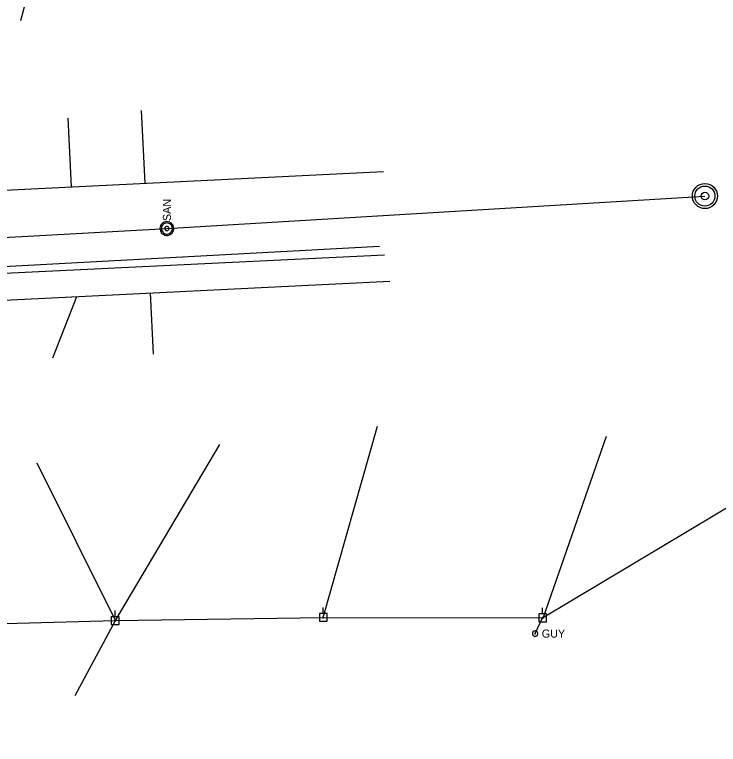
# Model space of a CAD drawing. Extents: x 596028 to 606371, y 330010 to 403088.
# Drawn here: x 605113.7 to 605450, y 333973.9 to 334322.4 of the extents above; entities that cross this region are included whole.
import ezdxf

# ---------------------------------------------------------------- set-up
doc = ezdxf.new("R2010")
doc.units = 0
for name, color, linetype in [('E_UTL_EGuyWire', 7, 'Continuous'), ('E_UTL_EPowerPole', 7, 'Continuous'), ('E_UTL_G_UG', 7, 'Continuous'), ('E_UTL_Overhead', 7, 'Continuous'), ('E_UTL_SAN_MH', 7, 'Continuous'), ('E_UTL_SAN_UG', 7, 'Continuous'), ('E_UTL_W_UG', 7, 'Continuous')]:
    doc.layers.add(name, color=color, linetype=linetype)

msp = doc.modelspace()

# ---------------------------------------------------------------- linework, layer by layer
at = {"layer": 'E_UTL_EGuyWire'}
msp.add_line((605362.42, 334026.83), (605366.02, 334034.35), dxfattribs=at)
for points in [[(605363.7, 334026.83), (605363.68, 334027.07), (605363.61, 334027.31), (605363.5, 334027.53), (605363.34, 334027.72), (605363.16, 334027.88), (605362.95, 334028), (605362.72, 334028.08), (605362.48, 334028.11), (605362.23, 334028.1), (605362, 334028.04), (605361.77, 334027.94), (605361.58, 334027.8), (605361.41, 334027.63), (605361.28, 334027.42), (605361.18, 334027.19), (605361.14, 334026.95), (605361.14, 334026.71), (605361.18, 334026.47), (605361.28, 334026.24), (605361.41, 334026.04), (605361.58, 334025.86), (605361.77, 334025.72), (605362, 334025.62), (605362.23, 334025.56), (605362.48, 334025.55), (605362.72, 334025.58), (605362.95, 334025.66), (605363.16, 334025.79), (605363.34, 334025.95), (605363.5, 334026.14), (605363.61, 334026.36), (605363.68, 334026.59), (605363.7, 334026.83)], [(605362.58, 334026.83), (605362.57, 334026.86), (605362.56, 334026.89), (605362.55, 334026.92), (605362.53, 334026.94), (605362.51, 334026.96), (605362.48, 334026.98), (605362.45, 334026.99), (605362.42, 334026.99), (605362.39, 334026.99), (605362.36, 334026.98), (605362.34, 334026.97), (605362.31, 334026.95), (605362.29, 334026.93), (605362.27, 334026.91), (605362.26, 334026.88), (605362.26, 334026.85), (605362.26, 334026.82), (605362.26, 334026.79), (605362.27, 334026.76), (605362.29, 334026.73), (605362.31, 334026.71), (605362.34, 334026.69), (605362.36, 334026.68), (605362.39, 334026.67), (605362.42, 334026.67), (605362.45, 334026.68), (605362.48, 334026.69), (605362.51, 334026.7), (605362.53, 334026.72), (605362.55, 334026.75), (605362.56, 334026.77), (605362.57, 334026.8), (605362.58, 334026.83)]]:
    msp.add_lwpolyline(points, dxfattribs=at)
at = {"layer": 'E_UTL_EPowerPole'}
for points in [[(605261.2, 334036.42), (605261.2, 334039.33)], [(605365.99, 334036.19), (605365.99, 334039.1)], [(605163.64, 334034.89), (605159.95, 334034.89)], [(605159.95, 334034.89), (605159.95, 334031.2)], [(605161.8, 334034.89), (605161.8, 334037.8)], [(605163.64, 334031.2), (605163.64, 334034.89)], [(605263.04, 334036.42), (605259.35, 334036.42)], [(605259.35, 334036.42), (605259.35, 334032.73)], [(605261.47, 334034.58), (605261.46, 334034.62), (605261.45, 334034.67), (605261.43, 334034.71), (605261.4, 334034.74), (605261.37, 334034.77), (605261.33, 334034.8), (605261.29, 334034.81), (605261.24, 334034.82), (605261.2, 334034.82), (605261.15, 334034.81), (605261.11, 334034.79), (605261.07, 334034.76), (605261.04, 334034.73), (605261.02, 334034.69), (605261, 334034.65), (605260.99, 334034.6), (605260.99, 334034.56), (605261, 334034.51), (605261.02, 334034.47), (605261.04, 334034.43), (605261.07, 334034.4), (605261.11, 334034.37), (605261.15, 334034.35), (605261.2, 334034.34), (605261.24, 334034.34), (605261.29, 334034.35), (605261.33, 334034.36), (605261.37, 334034.39), (605261.4, 334034.42), (605261.43, 334034.45), (605261.45, 334034.49), (605261.46, 334034.53), (605261.47, 334034.58)], [(605263.04, 334032.73), (605263.04, 334036.42)], [(605367.83, 334036.19), (605364.14, 334036.19)], [(605364.14, 334036.19), (605364.14, 334032.5)], [(605366.26, 334034.35), (605366.25, 334034.39), (605366.24, 334034.44), (605366.22, 334034.48), (605366.19, 334034.51), (605366.16, 334034.54), (605366.12, 334034.57), (605366.08, 334034.58), (605366.03, 334034.59), (605365.99, 334034.59), (605365.94, 334034.58), (605365.9, 334034.56), (605365.86, 334034.53), (605365.83, 334034.5), (605365.81, 334034.46), (605365.79, 334034.42), (605365.78, 334034.37), (605365.78, 334034.33), (605365.79, 334034.28), (605365.81, 334034.24), (605365.83, 334034.2), (605365.86, 334034.17), (605365.9, 334034.14), (605365.94, 334034.12), (605365.99, 334034.11), (605366.03, 334034.11), (605366.08, 334034.12), (605366.12, 334034.13), (605366.16, 334034.16), (605366.19, 334034.19), (605366.22, 334034.22), (605366.24, 334034.26), (605366.25, 334034.3), (605366.26, 334034.35)], [(605367.83, 334032.5), (605367.83, 334036.19)], [(605159.95, 334031.2), (605163.64, 334031.2)], [(605162.07, 334033.05), (605162.06, 334033.09), (605162.05, 334033.14), (605162.03, 334033.18), (605162, 334033.21), (605161.97, 334033.24), (605161.93, 334033.27), (605161.89, 334033.28), (605161.84, 334033.29), (605161.8, 334033.29), (605161.75, 334033.28), (605161.71, 334033.26), (605161.67, 334033.23), (605161.64, 334033.2), (605161.62, 334033.16), (605161.6, 334033.12), (605161.59, 334033.07), (605161.59, 334033.03), (605161.6, 334032.98), (605161.62, 334032.94), (605161.64, 334032.9), (605161.67, 334032.87), (605161.71, 334032.84), (605161.75, 334032.82), (605161.8, 334032.81), (605161.84, 334032.81), (605161.89, 334032.82), (605161.93, 334032.83), (605161.97, 334032.86), (605162, 334032.89), (605162.03, 334032.92), (605162.05, 334032.96), (605162.06, 334033), (605162.07, 334033.05)], [(605259.35, 334032.73), (605263.04, 334032.73)], [(605364.14, 334032.5), (605367.83, 334032.5)]]:
    msp.add_lwpolyline(points, dxfattribs=at)
at = {"layer": 'E_UTL_G_UG'}
for p, q in [((605176.07, 334241.9), (605174.36, 334276.62)), ((605140.91, 334240.17), (605139.3, 334272.95)), ((605102.33, 334238.28), (605290.02, 334247.49)), ((605095.32, 334198.25), (605290.47, 334207.64)), ((605095.32, 334198.25), (605290.47, 334207.64)), ((605052.89, 334183.33), (605293.1, 334195.11)), ((605132.09, 334158.54), (605143.55, 334187.78)), ((605180.08, 334160.18), (605178.64, 334189.5))]:
    msp.add_line(p, q, dxfattribs=at)
at = {"layer": 'E_UTL_Overhead'}
for p, q in [((605116.78, 334319.62), (605144.8, 334431.52)), ((605261.23, 334034.58), (605287.06, 334125.88)), ((605366.24, 334034.27), (605396.52, 334121.05)), ((605161.9, 334033.05), (605211.78, 334117.13)), ((605161.9, 334033.05), (605124.58, 334108.22)), ((605142.68, 333997.29), (605161.9, 334033.05))]:
    msp.add_line(p, q, dxfattribs=at)
msp.add_lwpolyline([(605062.13, 334030.34), (605161.83, 334033.05), (605261.23, 334034.58), (605366.02, 334034.35), (605490.67, 334108.9), (605629.26, 334192.31), (605760.16, 334289.56), (605857.09, 334357.51), (605913.37, 334539.47)], dxfattribs=at)
at = {"layer": 'E_UTL_SAN_MH'}
for points in [[(605186.5, 334223.55), (605185.88, 334223.49), (605185.28, 334223.31), (605184.72, 334223.03), (605184.23, 334222.64), (605183.82, 334222.16), (605183.5, 334221.62), (605183.3, 334221.03), (605183.21, 334220.41), (605183.24, 334219.78), (605183.38, 334219.17), (605183.65, 334218.6), (605184.01, 334218.09), (605184.46, 334217.66), (605184.99, 334217.32), (605185.57, 334217.08), (605186.19, 334216.96), (605186.82, 334216.96), (605187.43, 334217.08), (605188.02, 334217.32), (605188.54, 334217.66), (605189, 334218.09), (605189.36, 334218.6), (605189.62, 334219.17), (605189.77, 334219.78), (605189.8, 334220.41), (605189.71, 334221.03), (605189.51, 334221.62), (605189.19, 334222.16), (605188.78, 334222.64), (605188.29, 334223.03), (605187.73, 334223.31), (605187.13, 334223.49), (605186.5, 334223.55)], [(605186.5, 334222.89), (605186, 334222.84), (605185.52, 334222.7), (605185.08, 334222.47), (605184.68, 334222.16), (605184.35, 334221.78), (605184.1, 334221.35), (605183.94, 334220.87), (605183.87, 334220.38), (605183.89, 334219.87), (605184.01, 334219.39), (605184.22, 334218.93), (605184.51, 334218.52), (605184.87, 334218.17), (605185.29, 334217.9), (605185.76, 334217.72), (605186.25, 334217.62), (605186.75, 334217.62), (605187.25, 334217.72), (605187.71, 334217.9), (605188.14, 334218.17), (605188.5, 334218.52), (605188.79, 334218.93), (605189, 334219.39), (605189.12, 334219.87), (605189.14, 334220.38), (605189.07, 334220.87), (605188.9, 334221.35), (605188.65, 334221.78), (605188.33, 334222.16), (605187.93, 334222.47), (605187.48, 334222.7), (605187, 334222.84), (605186.5, 334222.89)], [(605186.5, 334221.24), (605186.32, 334221.22), (605186.14, 334221.17), (605185.97, 334221.08), (605185.82, 334220.97), (605185.7, 334220.82), (605185.6, 334220.66), (605185.54, 334220.48), (605185.51, 334220.3), (605185.52, 334220.11), (605185.57, 334219.93), (605185.65, 334219.75), (605185.76, 334219.6), (605185.89, 334219.47), (605186.05, 334219.37), (605186.22, 334219.3), (605186.41, 334219.26), (605186.6, 334219.26), (605186.78, 334219.3), (605186.96, 334219.37), (605187.12, 334219.47), (605187.25, 334219.6), (605187.36, 334219.75), (605187.44, 334219.93), (605187.48, 334220.11), (605187.49, 334220.3), (605187.47, 334220.48), (605187.4, 334220.66), (605187.31, 334220.82), (605187.19, 334220.97), (605187.04, 334221.08), (605186.87, 334221.17), (605186.69, 334221.22), (605186.5, 334221.24)]]:
    msp.add_lwpolyline(points, dxfattribs=at)
for radius in [6, 4.8, 1.8]:
    msp.add_circle((605443.55, 334235.75), radius, dxfattribs=at)
at = {"layer": 'E_UTL_SAN_UG'}
for p, q in [((605186.48, 334220.25), (605443.55, 334235.75)), ((604916.64, 334205.57), (605186.48, 334220.25))]:
    msp.add_line(p, q, dxfattribs=at)
at = {"layer": 'E_UTL_W_UG'}
msp.add_line((605096.59, 334201.48), (605288.08, 334211.76), dxfattribs=at)
for radius, start, end in [(4094.72, 293.47118, 313.14982), (3903.06, 293.46346, 305.86136)]:
    msp.add_arc((603570.96, 337309.26), radius, start, end, dxfattribs=at)

# ---------------------------------------------------------------- texts
at = {"layer": 'E_UTL_EGuyWire'}
msp.add_text('GUY', height=3.85, dxfattribs=at).set_placement((605365.62, 334024.91))
at = {"layer": 'E_UTL_SAN_MH'}
msp.add_text('SAN', height=3.849, rotation=90, dxfattribs=at).set_placement((605188.45, 334223.81))

doc.saveas('drawing.dxf')
